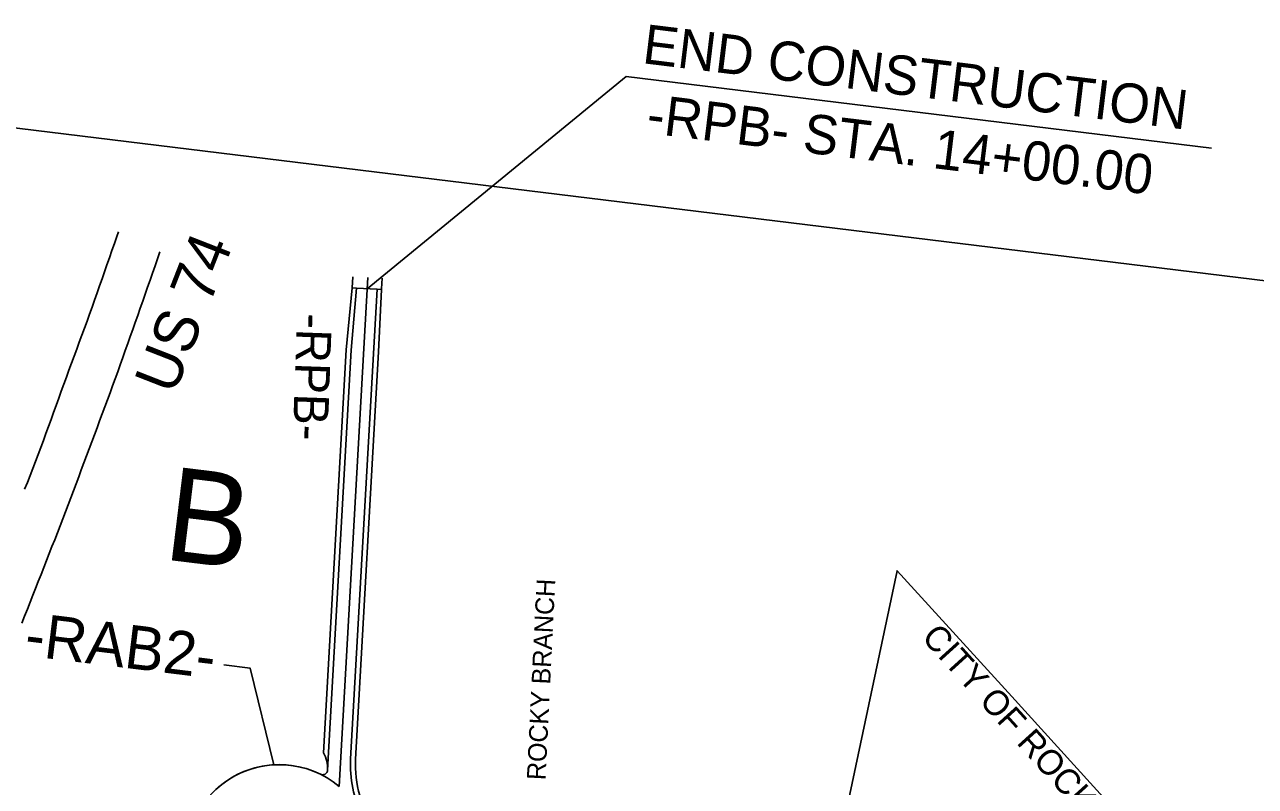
# Model space of a CAD drawing. Extents: x 1756435 to 1766932, y 416863 to 426859.
# Drawn here: x 1762835 to 1763823, y 423897 to 424508 of the extents above; entities that cross this region are included whole.
import ezdxf

# ---------------------------------------------------------------- set-up
doc = ezdxf.new("R2010")
doc.units = 0
for name, color, linetype in [('Exist Boundary City Limits', 7, 'Continuous'), ('Exist Hydro Stream or Body of Water Text', 7, 'Continuous'), ('Exist Roads EOP', 7, 'Continuous'), ('Prop Dimension Text', 7, 'Continuous'), ('Prop Horizontal Alignment', 7, 'Continuous'), ('Prop Horizontal Alignment Station Label', 7, 'Continuous'), ('Prop Shade Light', 7, 'Continuous'), ('Sheet Data Field CELL', 7, 'Continuous'), ('Sheet Plan CELL', 7, 'Continuous')]:
    doc.layers.add(name, color=color, linetype=linetype)

msp = doc.modelspace()

# ---------------------------------------------------------------- linework, layer by layer
at = {"layer": 'Exist Boundary City Limits'}
msp.add_lwpolyline([(1763808.64, 423769.81), (1763627.49, 423968.89), (1763535.51, 424069.97), (1763478.5, 423801.07), (1763652.88, 423779.73), (1763689.95, 423781.03), (1763764.16, 423763.14), (1763820.91, 423756.2), (1763808.64, 423769.81), (1763808.64, 423769.81)], dxfattribs=at)
at = {"layer": 'Exist Roads EOP'}
for points in [[(1762834.92, 424135.29), (1762837.14, 424140.87), (1762839.35, 424146.44), (1762841.56, 424152.02), (1762843.75, 424157.61), (1762845.83, 424163.23), (1762847.9, 424168.86), (1762849.96, 424174.49), (1762852.03, 424180.12), (1762854.1, 424185.76), (1762856.16, 424191.39), (1762858.22, 424197.03), (1762860.27, 424202.66), (1762862.32, 424208.3), (1762864.37, 424213.94), (1762866.42, 424219.57), (1762868.47, 424225.21), (1762870.53, 424230.85), (1762872.58, 424236.48), (1762874.66, 424242.11), (1762876.74, 424247.74), (1762878.81, 424253.37), (1762880.89, 424258.99), (1762882.97, 424264.62), (1762885.05, 424270.25), (1762887.11, 424275.88), (1762889.12, 424281.53), (1762891.11, 424287.19), (1762893.09, 424292.86), (1762895.07, 424298.52), (1762897.06, 424304.18), (1762899.04, 424309.84), (1762901.02, 424315.5), (1762903.01, 424321.16), (1762904.99, 424326.83), (1762906.97, 424332.49), (1762908.95, 424338.15), (1762910.22, 424341.79)], [(1762943.56, 424325.84), (1762941.58, 424320.17), (1762939.61, 424314.51), (1762937.63, 424308.84), (1762935.65, 424303.18), (1762933.67, 424297.52), (1762931.69, 424291.85), (1762929.71, 424286.19), (1762927.73, 424280.53), (1762925.75, 424274.86), (1762923.77, 424269.2), (1762921.78, 424263.54), (1762919.78, 424257.89), (1762917.77, 424252.24), (1762915.76, 424246.58), (1762913.75, 424240.93), (1762911.74, 424235.28), (1762909.73, 424229.63), (1762907.69, 424223.98), (1762905.6, 424218.36), (1762903.5, 424212.74), (1762901.41, 424207.12), (1762899.32, 424201.49), (1762897.23, 424195.87), (1762895.13, 424190.25), (1762893.04, 424184.63), (1762890.95, 424179), (1762888.86, 424173.38), (1762886.76, 424167.76), (1762884.65, 424162.14), (1762882.54, 424156.53), (1762880.43, 424150.91), (1762878.32, 424145.3), (1762876.21, 424139.68), (1762874.09, 424134.07), (1762871.98, 424128.45), (1762869.87, 424122.84), (1762867.76, 424117.23), (1762865.64, 424111.61), (1762863.49, 424106.01), (1762861.29, 424100.43), (1762859.09, 424094.85), (1762856.89, 424089.27), (1762854.7, 424083.69), (1762852.5, 424078.11), (1762850.3, 424072.52), (1762848.1, 424066.94), (1762845.9, 424061.36), (1762843.7, 424055.78), (1762841.5, 424050.2), (1762839.31, 424044.61), (1762837.12, 424039.03), (1762834.93, 424033.44), (1762832.75, 424027.86)], [(1763097.93, 424296.9), (1763098.33, 424305.85)], [(1763121.96, 424304.61), (1763121.58, 424296.15), (1763121.55, 424295.57)]]:
    msp.add_lwpolyline(points, dxfattribs=at)
at = {"layer": 'Prop Horizontal Alignment'}
msp.add_line((1763087.44, 423896.86), (1763110.39, 424305.26), dxfattribs=at)
msp.add_arc((1763039.37, 423839.28), 75, 50.14449, 192.48849, dxfattribs=at)
at = {"layer": 'Prop Horizontal Alignment Station Label'}
for p, q in [((1763109.88, 424296.23), (1763317.9, 424466.5)), ((1763317.9, 424466.5), (1763787.93, 424408.99))]:
    msp.add_line(p, q, dxfattribs=at)
msp.add_lwpolyline([(1762994.76, 423994.41), (1763015.89, 423991.82), (1763035.11, 423914.16)], dxfattribs=at)
at = {"layer": 'Prop Shade Light'}
for p, q in [((1763097.93, 424296.9), (1763093.1, 424247.09)), ((1763117.87, 424295.78), (1763096.69, 423918.93)), ((1763096.69, 423918.93), (1763117.87, 424295.78)), ((1763097.09, 424246.87), (1763101.34, 424296.71)), ((1763101.34, 424296.71), (1763097.09, 424246.87)), ((1763101.34, 424296.71), (1763097.93, 424296.9)), ((1763117.87, 424295.78), (1763101.34, 424296.71)), ((1763121.55, 424295.57), (1763117.87, 424295.78)), ((1763119.05, 424245.63), (1763121.55, 424295.57)), ((1763093.1, 424247.09), (1763074.93, 423923.75)), ((1763078.16, 423909.98), (1763097.09, 424246.87)), ((1763097.09, 424246.87), (1763078.16, 423909.98)), ((1763100.69, 423918.7), (1763119.05, 424245.63))]:
    msp.add_line(p, q, dxfattribs=at)
for centre, radius, start, end in [((1763053.2, 423911.38), 25, 356.78413, 29.64401), ((1763039.37, 423839.28), 75, 63.87018, 137.39356), ((1763186.55, 423913.88), 90, 176.78413, 206.87822), ((1763186.55, 423913.88), 90, 176.78413, 206.87822), ((1763186.55, 423913.88), 86, 176.78413, 196.46889), ((1763074.17, 423910.21), 4, 243.87018, 356.78413)]:
    msp.add_arc(centre, radius, start, end, dxfattribs=at)
at = {"layer": 'Sheet Plan CELL'}
msp.add_lwpolyline([(1762817.94, 424426.51), (1764168.29, 424261.27), (1764040.75, 423219.04), (1762690.4, 423384.28)], dxfattribs=at)

# ---------------------------------------------------------------- texts
at = {"layer": 'Exist Hydro Stream or Body of Water Text'}
msp.add_text('ROCKY BRANCH', height=15, rotation=87.17993, dxfattribs=at).set_placement((1763253.11, 423901.62))
at = {"layer": 'Prop Dimension Text'}
msp.add_text('B', height=75, rotation=353.0234, dxfattribs=at).set_placement((1762944.98, 424079.22))
at = {"layer": 'Sheet Data Field CELL'}
for s, height, rotation, p in [('US 74', 35, 68.65088, (1762954.96, 424210.06)), ('-RPB-', 28, 267.99588, (1763053.74, 424276.84)), ('-RAB2-', 35, 353.0234, (1762833.94, 424001.95))]:
    msp.add_text(s, height=height, rotation=rotation, dxfattribs=at).set_placement(p)
at = {"layer": 'Sheet Plan CELL'}
for s, height, rotation, p in [('END CONSTRUCTION', 31.5, 353.02435, (1763330.15, 424477.37)), ('-RPB- STA. 14+00.00', 31.5, 353.02435, (1763333.31, 424421.33)), ('CITY OF ROCKINGHAM', 20.16, 312.17419, (1763554.33, 424015.91))]:
    msp.add_text(s, height=height, rotation=rotation, dxfattribs=at).set_placement(p)

doc.saveas('drawing.dxf')
